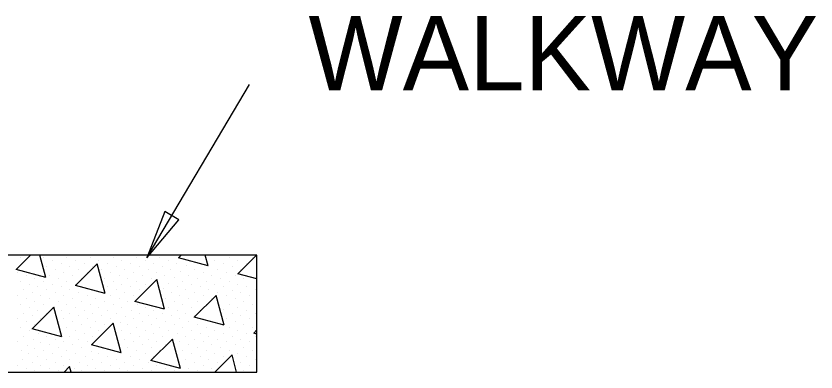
# Model space of a CAD drawing. Extents: x 12.65 to 19.62, y 5.94 to 15.74.
# Drawn here: x 14.092 to 14.736, y 8.82 to 9.107 of the extents above; entities that cross this region are included whole.
import ezdxf

# ---------------------------------------------------------------- set-up
doc = ezdxf.new("R2010")
doc.units = 0
for name, color, linetype in [('DETL-DIMS', 7, 'Continuous'), ('DETL-LINE', 7, 'Continuous'), ('DETL-NOTE', 7, 'Continuous')]:
    doc.layers.add(name, color=color, linetype=linetype)

msp = doc.modelspace()

# ---------------------------------------------------------------- linework, layer by layer
at = {"layer": 'DETL-DIMS'}
msp.add_line((14.19732, 8.913), (14.27968, 9.05204), dxfattribs=at)
msp.add_lwpolyline([(14.22284, 8.943), (14.21148, 8.9498), (14.19696, 8.91232)], close=True, dxfattribs=at)
at = {"layer": 'DETL-LINE'}
for p, q in [((14.28568, 8.91452), (14.08556, 8.91452)), ((14.0918, 8.90296), (14.10332, 8.91452)), ((14.09532, 8.91232), (14.09532, 8.91232)), ((14.11576, 8.89656), (14.11092, 8.91452)), ((14.114, 8.91232), (14.114, 8.91232)), ((14.12104, 8.90992), (14.12104, 8.90992)), ((14.13272, 8.91232), (14.13272, 8.91232)), ((14.13968, 8.90992), (14.13968, 8.90992)), ((14.1514, 8.91232), (14.1514, 8.91232)), ((14.15832, 8.90992), (14.15832, 8.90992)), ((14.17004, 8.91232), (14.17004, 8.91232)), ((14.177, 8.90992), (14.177, 8.90992)), ((14.18868, 8.91232), (14.18868, 8.91232)), ((14.19572, 8.90992), (14.19572, 8.90992)), ((14.20736, 8.91232), (14.20736, 8.91232)), ((14.2144, 8.90992), (14.2144, 8.90992)), ((14.22248, 8.9124), (14.2246, 8.91452)), ((14.24632, 8.90596), (14.22248, 8.9124)), ((14.23304, 8.90992), (14.23304, 8.90992)), ((14.24632, 8.90596), (14.24404, 8.91452)), ((14.24468, 8.91232), (14.24468, 8.91232)), ((14.25172, 8.90992), (14.25172, 8.90992)), ((14.2634, 8.91232), (14.2634, 8.91232)), ((14.27028, 8.89956), (14.28524, 8.91452)), ((14.27036, 8.90992), (14.27036, 8.90992)), ((14.28208, 8.91232), (14.28208, 8.91232)), ((14.28568, 8.82044), (14.28568, 8.91452)), ((14.11636, 8.90528), (14.11636, 8.90528)), ((14.12808, 8.90764), (14.12808, 8.90764)), ((14.135, 8.90528), (14.135, 8.90528)), ((14.13968, 8.89012), (14.15712, 8.90764)), ((14.14672, 8.90764), (14.14672, 8.90764)), ((14.15368, 8.90528), (14.15368, 8.90528)), ((14.16352, 8.8838), (14.15712, 8.90764)), ((14.16536, 8.90764), (14.16536, 8.90764)), ((14.17232, 8.90528), (14.17232, 8.90528)), ((14.18404, 8.90764), (14.18404, 8.90764)), ((14.19108, 8.90528), (14.19108, 8.90528)), ((14.20268, 8.90764), (14.20268, 8.90764)), ((14.20972, 8.90528), (14.20972, 8.90528)), ((14.22056, 8.90748), (14.22056, 8.90748)), ((14.22872, 8.90596), (14.22872, 8.90596)), ((14.24, 8.90764), (14.24, 8.90764)), ((14.24704, 8.90528), (14.24704, 8.90528)), ((14.25876, 8.90764), (14.25876, 8.90764)), ((14.26568, 8.90528), (14.26568, 8.90528)), ((14.2774, 8.90764), (14.2774, 8.90764)), ((14.11576, 8.89656), (14.0918, 8.90296)), ((14.09304, 8.9006), (14.09304, 8.9006)), ((14.1, 8.89832), (14.1, 8.89832)), ((14.11872, 8.89832), (14.11872, 8.89832)), ((14.1234, 8.90296), (14.1234, 8.90296)), ((14.13036, 8.9006), (14.13036, 8.9006)), ((14.1374, 8.89832), (14.1374, 8.89832)), ((14.14204, 8.90296), (14.14204, 8.90296)), ((14.149, 8.9006), (14.149, 8.9006)), ((14.16072, 8.90296), (14.16072, 8.90296)), ((14.16768, 8.9006), (14.16768, 8.9006)), ((14.17472, 8.89832), (14.17472, 8.89832)), ((14.17936, 8.90296), (14.17936, 8.90296)), ((14.1864, 8.9006), (14.1864, 8.9006)), ((14.19336, 8.89832), (14.19336, 8.89832)), ((14.19804, 8.90296), (14.19804, 8.90296)), ((14.20508, 8.9006), (14.20508, 8.9006)), ((14.21124, 8.89812), (14.21124, 8.89812)), ((14.21588, 8.9028), (14.21588, 8.9028)), ((14.22408, 8.90132), (14.22408, 8.90132)), ((14.23068, 8.89832), (14.23068, 8.89832)), ((14.23532, 8.90296), (14.23532, 8.90296)), ((14.24236, 8.9006), (14.24236, 8.9006)), ((14.24932, 8.89832), (14.24932, 8.89832)), ((14.254, 8.90296), (14.254, 8.90296)), ((14.26104, 8.9006), (14.26104, 8.9006)), ((14.26808, 8.89832), (14.26808, 8.89832)), ((14.28568, 8.8954), (14.27028, 8.89956)), ((14.27272, 8.90296), (14.27272, 8.90296)), ((14.09532, 8.89364), (14.09532, 8.89364)), ((14.10236, 8.89128), (14.10236, 8.89128)), ((14.10704, 8.89592), (14.10704, 8.89592)), ((14.114, 8.89364), (14.114, 8.89364)), ((14.12104, 8.89128), (14.12104, 8.89128)), ((14.12568, 8.89592), (14.12568, 8.89592)), ((14.13272, 8.89364), (14.13272, 8.89364)), ((14.13968, 8.89128), (14.13968, 8.89128)), ((14.14436, 8.89592), (14.14436, 8.89592)), ((14.163, 8.89592), (14.163, 8.89592)), ((14.17004, 8.89364), (14.17004, 8.89364)), ((14.177, 8.89128), (14.177, 8.89128)), ((14.18164, 8.89592), (14.18164, 8.89592)), ((14.18748, 8.87736), (14.20496, 8.89488)), ((14.18868, 8.89364), (14.18868, 8.89364)), ((14.19572, 8.89128), (14.19572, 8.89128)), ((14.2004, 8.89592), (14.2004, 8.89592)), ((14.21132, 8.87096), (14.20496, 8.89488)), ((14.21476, 8.89196), (14.21476, 8.89196)), ((14.2194, 8.89664), (14.2194, 8.89664)), ((14.226, 8.89364), (14.226, 8.89364)), ((14.23304, 8.89128), (14.23304, 8.89128)), ((14.23772, 8.89592), (14.23772, 8.89592)), ((14.24468, 8.89364), (14.24468, 8.89364)), ((14.25172, 8.89128), (14.25172, 8.89128)), ((14.25636, 8.89592), (14.25636, 8.89592)), ((14.2634, 8.89364), (14.2634, 8.89364)), ((14.27036, 8.89108), (14.27036, 8.89108)), ((14.27504, 8.89576), (14.27504, 8.89576)), ((14.09772, 8.8866), (14.09772, 8.8866)), ((14.10464, 8.88432), (14.10464, 8.88432)), ((14.10932, 8.889), (14.10932, 8.889)), ((14.11636, 8.8866), (14.11636, 8.8866)), ((14.1234, 8.88432), (14.1234, 8.88432)), ((14.12808, 8.889), (14.12808, 8.889)), ((14.135, 8.8866), (14.135, 8.8866)), ((14.16352, 8.8838), (14.13968, 8.89012)), ((14.14204, 8.88432), (14.14204, 8.88432)), ((14.16072, 8.88432), (14.16072, 8.88432)), ((14.16536, 8.889), (14.16536, 8.889)), ((14.17232, 8.8866), (14.17232, 8.8866)), ((14.17936, 8.88432), (14.17936, 8.88432)), ((14.18404, 8.889), (14.18404, 8.889)), ((14.19108, 8.8866), (14.19108, 8.8866)), ((14.21008, 8.88732), (14.21008, 8.88732)), ((14.21668, 8.88432), (14.21668, 8.88432)), ((14.22136, 8.889), (14.22136, 8.889)), ((14.2284, 8.8866), (14.2284, 8.8866)), ((14.23532, 8.88432), (14.23532, 8.88432)), ((14.24, 8.889), (14.24, 8.889)), ((14.24704, 8.8866), (14.24704, 8.8866)), ((14.254, 8.88432), (14.254, 8.88432)), ((14.25876, 8.889), (14.25876, 8.889)), ((14.26568, 8.88644), (14.26568, 8.88644)), ((14.27264, 8.88448), (14.27264, 8.88448)), ((14.27732, 8.88916), (14.27732, 8.88916)), ((14.28436, 8.8866), (14.28436, 8.8866)), ((14.09304, 8.88196), (14.09304, 8.88196)), ((14.1, 8.87964), (14.1, 8.87964)), ((14.11168, 8.88196), (14.11168, 8.88196)), ((14.11872, 8.87964), (14.11872, 8.87964)), ((14.13036, 8.88196), (14.13036, 8.88196)), ((14.1374, 8.87964), (14.1374, 8.87964)), ((14.149, 8.88196), (14.149, 8.88196)), ((14.15604, 8.87964), (14.15604, 8.87964)), ((14.16768, 8.88196), (14.16768, 8.88196)), ((14.17472, 8.87964), (14.17472, 8.87964)), ((14.1864, 8.88196), (14.1864, 8.88196)), ((14.212, 8.87964), (14.212, 8.87964)), ((14.22372, 8.88196), (14.22372, 8.88196)), ((14.23068, 8.87964), (14.23068, 8.87964)), ((14.23524, 8.86452), (14.25276, 8.88204)), ((14.24236, 8.88196), (14.24236, 8.88196)), ((14.24932, 8.87964), (14.24932, 8.87964)), ((14.2592, 8.8582), (14.25276, 8.88204)), ((14.26104, 8.88176), (14.26104, 8.88176)), ((14.268, 8.87984), (14.268, 8.87984)), ((14.27968, 8.88196), (14.27968, 8.88196)), ((14.09532, 8.875), (14.09532, 8.875)), ((14.10236, 8.8726), (14.10236, 8.8726)), ((14.10464, 8.8552), (14.12216, 8.87272)), ((14.10704, 8.87728), (14.10704, 8.87728)), ((14.114, 8.875), (14.114, 8.875)), ((14.12104, 8.8726), (14.12104, 8.8726)), ((14.12852, 8.84876), (14.12216, 8.87272)), ((14.12568, 8.87728), (14.12568, 8.87728)), ((14.13272, 8.875), (14.13272, 8.875)), ((14.13968, 8.8726), (14.13968, 8.8726)), ((14.14436, 8.87728), (14.14436, 8.87728)), ((14.1514, 8.875), (14.1514, 8.875)), ((14.15832, 8.8726), (14.15832, 8.8726)), ((14.163, 8.87728), (14.163, 8.87728)), ((14.17004, 8.875), (14.17004, 8.875)), ((14.177, 8.8726), (14.177, 8.8726)), ((14.18164, 8.87728), (14.18164, 8.87728)), ((14.21132, 8.87096), (14.18748, 8.87736)), ((14.18948, 8.87464), (14.18948, 8.87464)), ((14.19572, 8.8726), (14.19572, 8.8726)), ((14.2144, 8.8726), (14.2144, 8.8726)), ((14.21904, 8.87728), (14.21904, 8.87728)), ((14.226, 8.875), (14.226, 8.875)), ((14.23304, 8.8726), (14.23304, 8.8726)), ((14.23772, 8.87728), (14.23772, 8.87728)), ((14.24468, 8.875), (14.24468, 8.875)), ((14.26332, 8.87516), (14.26332, 8.87516)), ((14.27036, 8.8726), (14.27036, 8.8726)), ((14.27504, 8.87728), (14.27504, 8.87728)), ((14.28208, 8.875), (14.28208, 8.875)), ((14.09772, 8.86796), (14.09772, 8.86796)), ((14.10464, 8.86556), (14.10464, 8.86556)), ((14.10932, 8.87024), (14.10932, 8.87024)), ((14.11636, 8.86796), (14.11636, 8.86796)), ((14.12808, 8.87024), (14.12808, 8.87024)), ((14.135, 8.86796), (14.135, 8.86796)), ((14.14204, 8.86556), (14.14204, 8.86556)), ((14.14672, 8.87024), (14.14672, 8.87024)), ((14.15368, 8.86796), (14.15368, 8.86796)), ((14.16072, 8.86556), (14.16072, 8.86556)), ((14.16536, 8.87024), (14.16536, 8.87024)), ((14.17232, 8.86796), (14.17232, 8.86796)), ((14.18016, 8.86532), (14.18016, 8.86532)), ((14.18484, 8.86996), (14.18484, 8.86996)), ((14.19108, 8.86796), (14.19108, 8.86796)), ((14.19804, 8.86556), (14.19804, 8.86556)), ((14.20268, 8.87024), (14.20268, 8.87024)), ((14.20972, 8.86796), (14.20972, 8.86796)), ((14.21668, 8.86556), (14.21668, 8.86556)), ((14.22136, 8.87024), (14.22136, 8.87024)), ((14.2284, 8.86796), (14.2284, 8.86796)), ((14.23532, 8.86556), (14.23532, 8.86556)), ((14.24, 8.87024), (14.24, 8.87024)), ((14.25864, 8.87052), (14.25864, 8.87052)), ((14.26568, 8.86796), (14.26568, 8.86796)), ((14.27272, 8.86556), (14.27272, 8.86556)), ((14.2774, 8.87024), (14.2774, 8.87024)), ((14.28436, 8.86796), (14.28436, 8.86796)), ((14.09304, 8.86328), (14.09304, 8.86328)), ((14.1, 8.86092), (14.1, 8.86092)), ((14.10704, 8.85864), (14.10704, 8.85864)), ((14.11168, 8.86328), (14.11168, 8.86328)), ((14.12568, 8.85864), (14.12568, 8.85864)), ((14.13036, 8.86328), (14.13036, 8.86328)), ((14.1374, 8.86092), (14.1374, 8.86092)), ((14.14436, 8.85864), (14.14436, 8.85864)), ((14.149, 8.86328), (14.149, 8.86328)), ((14.15244, 8.84236), (14.16996, 8.85984)), ((14.15604, 8.86092), (14.15604, 8.86092)), ((14.163, 8.85864), (14.163, 8.85864)), ((14.16768, 8.86328), (14.16768, 8.86328)), ((14.17636, 8.83592), (14.16996, 8.85984)), ((14.17548, 8.86064), (14.17548, 8.86064)), ((14.18164, 8.85864), (14.18164, 8.85864)), ((14.1864, 8.86328), (14.1864, 8.86328)), ((14.19336, 8.86092), (14.19336, 8.86092)), ((14.2004, 8.85864), (14.2004, 8.85864)), ((14.20508, 8.86328), (14.20508, 8.86328)), ((14.212, 8.86092), (14.212, 8.86092)), ((14.21904, 8.85864), (14.21904, 8.85864)), ((14.22372, 8.86328), (14.22372, 8.86328)), ((14.23068, 8.86092), (14.23068, 8.86092)), ((14.2592, 8.8582), (14.23524, 8.86452)), ((14.23772, 8.85864), (14.23772, 8.85864)), ((14.24236, 8.86328), (14.24236, 8.86328)), ((14.24932, 8.86092), (14.24932, 8.86092)), ((14.25636, 8.85864), (14.25636, 8.85864)), ((14.26104, 8.86328), (14.26104, 8.86328)), ((14.26808, 8.86092), (14.26808, 8.86092)), ((14.27504, 8.85864), (14.27504, 8.85864)), ((14.27968, 8.86328), (14.27968, 8.86328)), ((14.09532, 8.85624), (14.09532, 8.85624)), ((14.10236, 8.85396), (14.10236, 8.85396)), ((14.12852, 8.84876), (14.10464, 8.8552)), ((14.13272, 8.85624), (14.13272, 8.85624)), ((14.13968, 8.85396), (14.13968, 8.85396)), ((14.1514, 8.85624), (14.1514, 8.85624)), ((14.15832, 8.85396), (14.15832, 8.85396)), ((14.17084, 8.856), (14.17084, 8.856)), ((14.177, 8.85396), (14.177, 8.85396)), ((14.18868, 8.85624), (14.18868, 8.85624)), ((14.19572, 8.85396), (14.19572, 8.85396)), ((14.20736, 8.85624), (14.20736, 8.85624)), ((14.2144, 8.85396), (14.2144, 8.85396)), ((14.226, 8.85624), (14.226, 8.85624)), ((14.23304, 8.85396), (14.23304, 8.85396)), ((14.24468, 8.85624), (14.24468, 8.85624)), ((14.25172, 8.85396), (14.25172, 8.85396)), ((14.2634, 8.85624), (14.2634, 8.85624)), ((14.27036, 8.85396), (14.27036, 8.85396)), ((14.28208, 8.85624), (14.28208, 8.85624)), ((14.28312, 8.85176), (14.28568, 8.85432)), ((14.09772, 8.84928), (14.09772, 8.84928)), ((14.10552, 8.84676), (14.10552, 8.84676)), ((14.1102, 8.8514), (14.1102, 8.8514)), ((14.11592, 8.84896), (14.11592, 8.84896)), ((14.1234, 8.84692), (14.1234, 8.84692)), ((14.12808, 8.8516), (14.12808, 8.8516)), ((14.135, 8.84928), (14.135, 8.84928)), ((14.14204, 8.84692), (14.14204, 8.84692)), ((14.14672, 8.8516), (14.14672, 8.8516)), ((14.15368, 8.84928), (14.15368, 8.84928)), ((14.17936, 8.84692), (14.17936, 8.84692)), ((14.18404, 8.8516), (14.18404, 8.8516)), ((14.19108, 8.84928), (14.19108, 8.84928)), ((14.19804, 8.84692), (14.19804, 8.84692)), ((14.20024, 8.8296), (14.21772, 8.847)), ((14.20268, 8.8516), (14.20268, 8.8516)), ((14.20972, 8.84928), (14.20972, 8.84928)), ((14.21668, 8.84692), (14.21668, 8.84692)), ((14.22416, 8.82316), (14.21772, 8.847)), ((14.22136, 8.8516), (14.22136, 8.8516)), ((14.2284, 8.84928), (14.2284, 8.84928)), ((14.23532, 8.84692), (14.23532, 8.84692)), ((14.24, 8.8516), (14.24, 8.8516)), ((14.24704, 8.84928), (14.24704, 8.84928)), ((14.254, 8.84692), (14.254, 8.84692)), ((14.25876, 8.8516), (14.25876, 8.8516)), ((14.26568, 8.84928), (14.26568, 8.84928)), ((14.27272, 8.84692), (14.27272, 8.84692)), ((14.2774, 8.8516), (14.2774, 8.8516)), ((14.28568, 8.85104), (14.28312, 8.85176)), ((14.28436, 8.84928), (14.28436, 8.84928)), ((14.09304, 8.84464), (14.09304, 8.84464)), ((14.10088, 8.84208), (14.10088, 8.84208)), ((14.1066, 8.8396), (14.1066, 8.8396)), ((14.11124, 8.84428), (14.11124, 8.84428)), ((14.11872, 8.84224), (14.11872, 8.84224)), ((14.12568, 8.83996), (14.12568, 8.83996)), ((14.13036, 8.84464), (14.13036, 8.84464)), ((14.1374, 8.84224), (14.1374, 8.84224)), ((14.14436, 8.83996), (14.14436, 8.83996)), ((14.149, 8.84464), (14.149, 8.84464)), ((14.17636, 8.83592), (14.15244, 8.84236)), ((14.17472, 8.84224), (14.17472, 8.84224)), ((14.18164, 8.83996), (14.18164, 8.83996)), ((14.1864, 8.84464), (14.1864, 8.84464)), ((14.19336, 8.84224), (14.19336, 8.84224)), ((14.2004, 8.83996), (14.2004, 8.83996)), ((14.20508, 8.84464), (14.20508, 8.84464)), ((14.212, 8.84224), (14.212, 8.84224)), ((14.22372, 8.84464), (14.22372, 8.84464)), ((14.23068, 8.84224), (14.23068, 8.84224)), ((14.23772, 8.83996), (14.23772, 8.83996)), ((14.24236, 8.84464), (14.24236, 8.84464)), ((14.24932, 8.84224), (14.24932, 8.84224)), ((14.25636, 8.83996), (14.25636, 8.83996)), ((14.26104, 8.84464), (14.26104, 8.84464)), ((14.26808, 8.84224), (14.26808, 8.84224)), ((14.27504, 8.83996), (14.27504, 8.83996)), ((14.27968, 8.84464), (14.27968, 8.84464)), ((14.0962, 8.8374), (14.0962, 8.8374)), ((14.10192, 8.83496), (14.10192, 8.83496)), ((14.10932, 8.83292), (14.10932, 8.83292)), ((14.114, 8.8376), (14.114, 8.8376)), ((14.12104, 8.83532), (14.12104, 8.83532)), ((14.12808, 8.83292), (14.12808, 8.83292)), ((14.13272, 8.8376), (14.13272, 8.8376)), ((14.13968, 8.83532), (14.13968, 8.83532)), ((14.14796, 8.83268), (14.14796, 8.83268)), ((14.1526, 8.83732), (14.1526, 8.83732)), ((14.15832, 8.83532), (14.15832, 8.83532)), ((14.16536, 8.83292), (14.16536, 8.83292)), ((14.17004, 8.8376), (14.17004, 8.8376)), ((14.177, 8.83532), (14.177, 8.83532)), ((14.18404, 8.83292), (14.18404, 8.83292)), ((14.18868, 8.8376), (14.18868, 8.8376)), ((14.19572, 8.83532), (14.19572, 8.83532)), ((14.20268, 8.83292), (14.20268, 8.83292)), ((14.20736, 8.8376), (14.20736, 8.8376)), ((14.226, 8.8376), (14.226, 8.8376)), ((14.23304, 8.83532), (14.23304, 8.83532)), ((14.24, 8.83292), (14.24, 8.83292)), ((14.24468, 8.8376), (14.24468, 8.8376)), ((14.25172, 8.83532), (14.25172, 8.83532)), ((14.2518, 8.82044), (14.2656, 8.83424)), ((14.25876, 8.83292), (14.25876, 8.83292)), ((14.2634, 8.8376), (14.2634, 8.8376)), ((14.26932, 8.82044), (14.2656, 8.83424)), ((14.27036, 8.83532), (14.27036, 8.83532)), ((14.2774, 8.83292), (14.2774, 8.83292)), ((14.28208, 8.8376), (14.28208, 8.8376)), ((14.09728, 8.83028), (14.09728, 8.83028)), ((14.10464, 8.82828), (14.10464, 8.82828)), ((14.11636, 8.83064), (14.11636, 8.83064)), ((14.1234, 8.82828), (14.1234, 8.82828)), ((14.135, 8.83064), (14.135, 8.83064)), ((14.1432, 8.828), (14.1432, 8.828)), ((14.15368, 8.83064), (14.15368, 8.83064)), ((14.16072, 8.82828), (14.16072, 8.82828)), ((14.17232, 8.83064), (14.17232, 8.83064)), ((14.17936, 8.82828), (14.17936, 8.82828)), ((14.19108, 8.83064), (14.19108, 8.83064)), ((14.19804, 8.82828), (14.19804, 8.82828)), ((14.22416, 8.82316), (14.20024, 8.8296)), ((14.2284, 8.83064), (14.2284, 8.83064)), ((14.23532, 8.82828), (14.23532, 8.82828)), ((14.24704, 8.83064), (14.24704, 8.83064)), ((14.254, 8.82828), (14.254, 8.82828)), ((14.27272, 8.82828), (14.27272, 8.82828)), ((14.28436, 8.83064), (14.28436, 8.83064)), ((14.08556, 8.82044), (14.28568, 8.82044)), ((14.0926, 8.82564), (14.0926, 8.82564)), ((14.1, 8.8236), (14.1, 8.8236)), ((14.10704, 8.82132), (14.10704, 8.82132)), ((14.11168, 8.82596), (14.11168, 8.82596)), ((14.11872, 8.8236), (14.11872, 8.8236)), ((14.12568, 8.82132), (14.12568, 8.82132)), ((14.13036, 8.82596), (14.13036, 8.82596)), ((14.13052, 8.82044), (14.13492, 8.82484)), ((14.13616, 8.82044), (14.13492, 8.82484)), ((14.13852, 8.82332), (14.13852, 8.82332)), ((14.14436, 8.82132), (14.14436, 8.82132)), ((14.149, 8.82596), (14.149, 8.82596)), ((14.15604, 8.8236), (14.15604, 8.8236)), ((14.163, 8.82132), (14.163, 8.82132)), ((14.16768, 8.82596), (14.16768, 8.82596)), ((14.17472, 8.8236), (14.17472, 8.8236)), ((14.18164, 8.82132), (14.18164, 8.82132)), ((14.1864, 8.82596), (14.1864, 8.82596)), ((14.19336, 8.8236), (14.19336, 8.8236)), ((14.2004, 8.82132), (14.2004, 8.82132)), ((14.20508, 8.82596), (14.20508, 8.82596)), ((14.212, 8.8236), (14.212, 8.8236)), ((14.21904, 8.82132), (14.21904, 8.82132)), ((14.22372, 8.82596), (14.22372, 8.82596)), ((14.23068, 8.8236), (14.23068, 8.8236)), ((14.23772, 8.82132), (14.23772, 8.82132)), ((14.24236, 8.82596), (14.24236, 8.82596)), ((14.24932, 8.8236), (14.24932, 8.8236)), ((14.26808, 8.8236), (14.26808, 8.8236)), ((14.27504, 8.82132), (14.27504, 8.82132)), ((14.27968, 8.82596), (14.27968, 8.82596))]:
    msp.add_line(p, q, dxfattribs=at)

# ---------------------------------------------------------------- texts
at = {"layer": 'DETL-NOTE'}
msp.add_text('WALKWAY', height=0.06, rotation=360, dxfattribs=at).set_placement((14.32716, 9.04724))

doc.saveas('drawing.dxf')
